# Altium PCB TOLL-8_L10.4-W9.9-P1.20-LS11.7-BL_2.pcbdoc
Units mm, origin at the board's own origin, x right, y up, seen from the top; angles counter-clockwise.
Board outline 22.84 x 25.35 mm, 2 copper layers (Top Layer, Bottom Layer), stack 0.07 mm thick; 1 components, 0 nets, 3 pads, 0 vias.
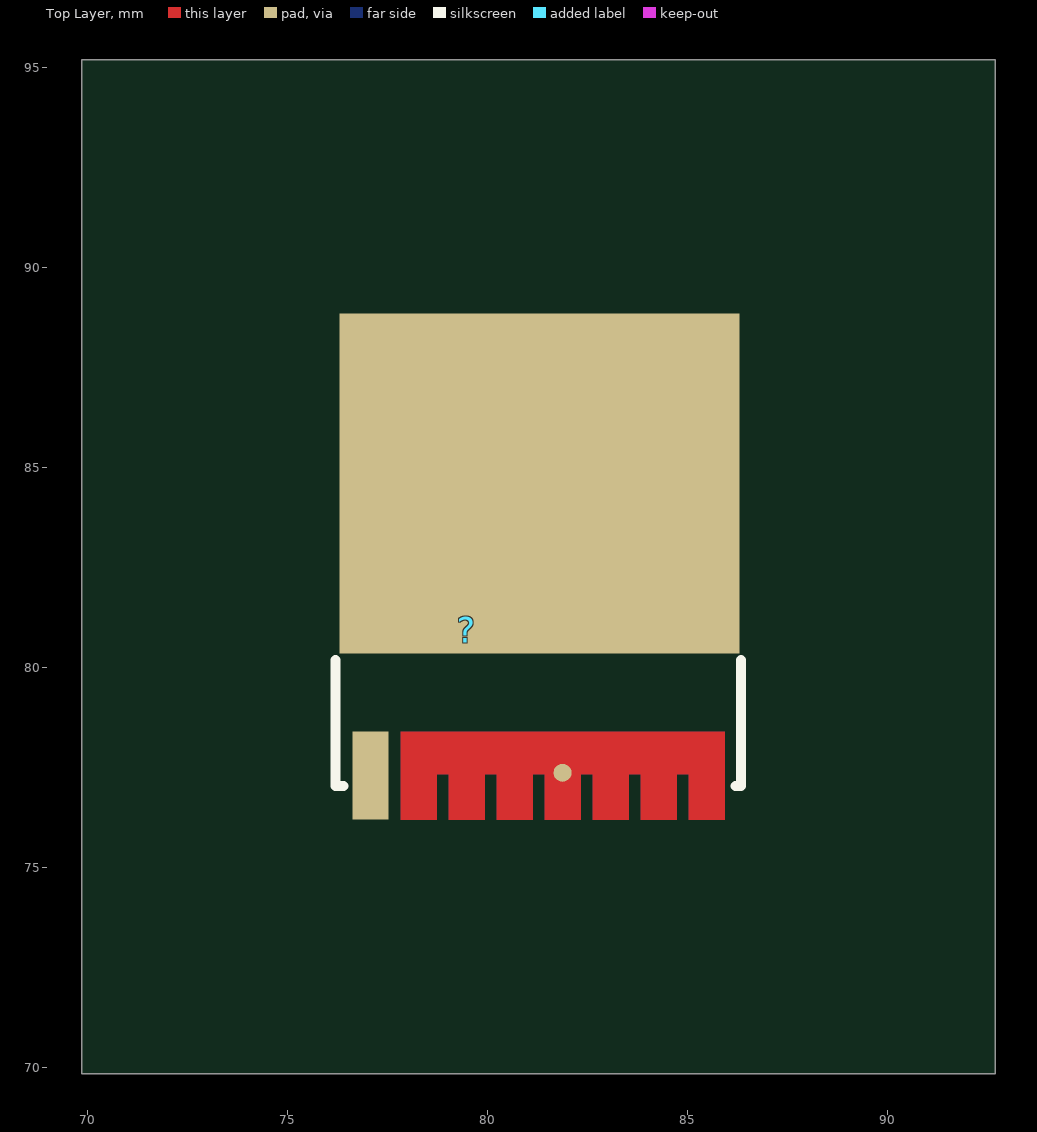
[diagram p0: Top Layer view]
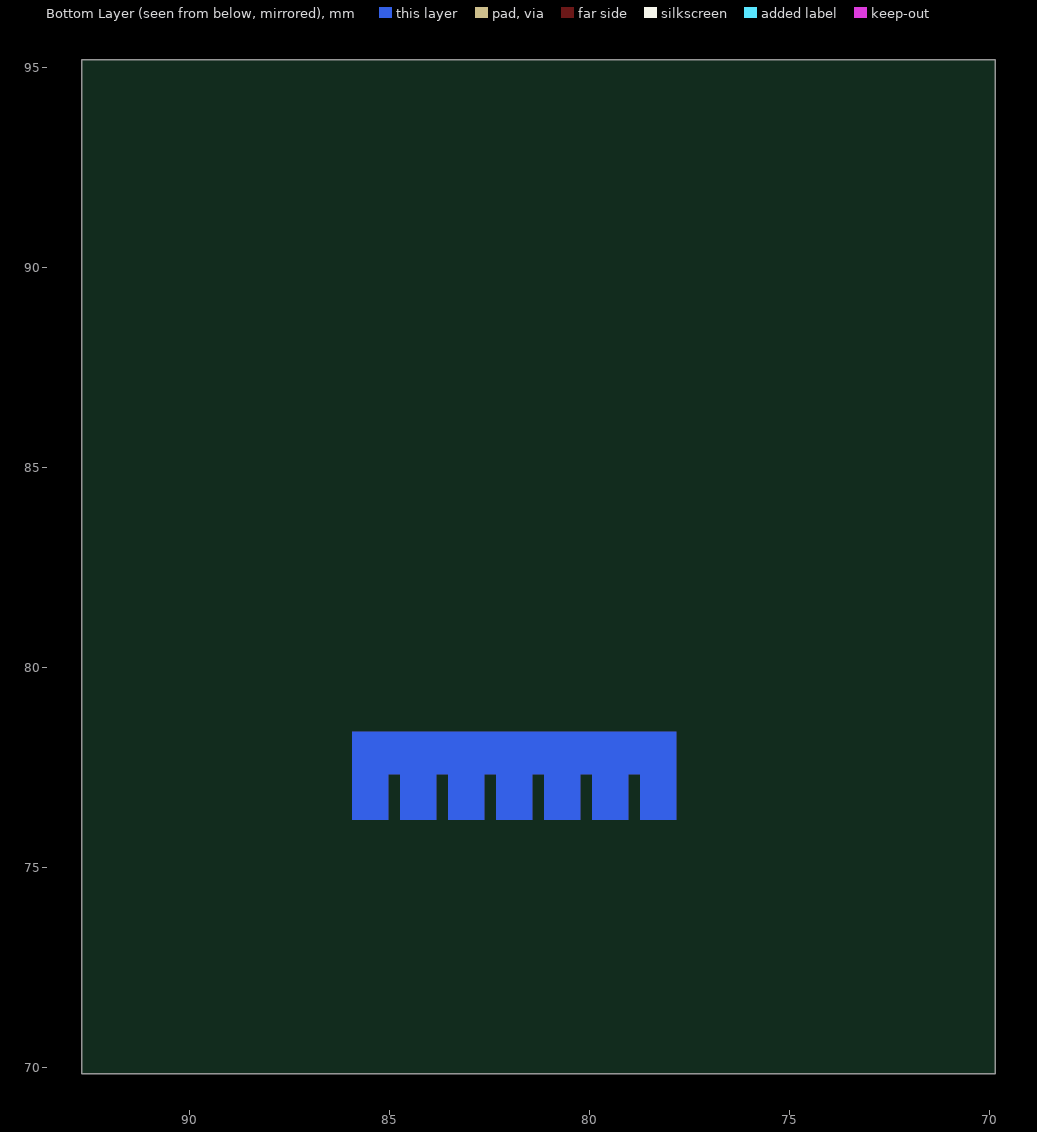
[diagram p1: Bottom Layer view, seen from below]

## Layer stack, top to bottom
Top Solder Mask Layer: solder mask 0.01, Dk 3.3
Top Layer: signal copper 0.035
Bottom Layer: signal copper 0.035
Bottom Solder Mask Layer: solder mask 0.01, Dk 3.3

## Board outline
92.69,69.85 69.85,69.85 69.85,95.2 92.69,95.2

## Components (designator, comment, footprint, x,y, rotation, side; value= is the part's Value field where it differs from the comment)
? "TOLL-8_L10.4-W9.9-P1.20-LS11.7-BL_2" TOLL-8_L10.4-W9.9-P1.20-LS11.7-BL_2 79.475,80.95 r0 top

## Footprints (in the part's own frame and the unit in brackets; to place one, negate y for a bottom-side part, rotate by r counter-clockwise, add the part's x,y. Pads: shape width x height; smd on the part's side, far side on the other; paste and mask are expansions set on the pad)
TOLL-8_L10.4-W9.9-P1.20-LS11.7-BL_2 [mm]
  rect 0.9x2.2 smd paste-100 mask+0.05: 1(-2.4,-3.65)
  round 0.451 smd: 2(2.4,-3.581)
  rect 10x8.5 smd paste-100 mask+0.05: 3(1.825,3.65)
  Top Layer region: -1.65,-2.55 -1.65,-4.75 -0.75,-4.75 -0.75,-3.615 -0.45,-3.615 -0.45,-4.75 0.45,-4.75 0.45,-3.615 0.75,-3.615 0.75,-4.75 1.65,-4.75 1.65,-3.615 1.95,-3.615 1.95,-4.75 2.85,-4.75 2.85,-3.615 3.15,-3.615 3.15,-4.75 4.05,-4.75 4.05,-3.615 4.35,-3.615 4.35,-4.75 5.25,-4.75 5.25,-3.615 5.55,-3.615 5.55,-4.75 6.45,-4.75 6.45,-3.615 6.45,-3.615 6.45,-2.551 6.45,-2.551 6.45,-2.55 5.55,-2.55 5.55,-2.551 5.25,-2.551 5.25,-2.55 4.35,-2.55 4.35,-2.551 4.05,-2.551 4.05,-2.55 3.15,-2.55 3.15,-2.551 2.85,-2.551 2.85,-2.55 1.95,-2.55 1.95,-2.551 1.65,-2.551 1.65,-2.55 0.75,-2.55 0.75,-2.551 0.45,-2.551 0.45,-2.55 -0.45,-2.55 -0.45,-2.551 -0.75,-2.551 -0.75,-2.55 -1.65,-2.55
  Bottom Layer region: -1.65,-2.55 -1.65,-4.75 -0.75,-4.75 -0.75,-3.615 -0.45,-3.615 -0.45,-4.75 0.45,-4.75 0.45,-3.615 0.75,-3.615 0.75,-4.75 1.65,-4.75 1.65,-3.615 1.95,-3.615 1.95,-4.75 2.85,-4.75 2.85,-3.615 3.15,-3.615 3.15,-4.75 4.05,-4.75 4.05,-3.615 4.35,-3.615 4.35,-4.75 5.25,-4.75 5.25,-3.615 5.55,-3.615 5.55,-4.75 6.45,-4.75 6.45,-3.615 6.45,-3.615 6.45,-2.551 6.45,-2.551 6.45,-2.55 5.55,-2.55 5.55,-2.551 5.25,-2.551 5.25,-2.55 4.35,-2.55 4.35,-2.551 4.05,-2.551 4.05,-2.55 3.15,-2.55 3.15,-2.551 2.85,-2.551 2.85,-2.55 1.95,-2.55 1.95,-2.551 1.65,-2.551 1.65,-2.55 0.75,-2.55 0.75,-2.551 0.45,-2.551 0.45,-2.55 -0.45,-2.55 -0.45,-2.551 -0.75,-2.551 -0.75,-2.55 -1.65,-2.55
  Multi-Layer region: -1.65,-2.55 -1.65,-4.75 -0.75,-4.75 -0.75,-3.615 -0.45,-3.615 -0.45,-4.75 0.45,-4.75 0.45,-3.615 0.75,-3.615 0.75,-4.75 1.65,-4.75 1.65,-3.615 1.95,-3.615 1.95,-4.75 2.85,-4.75 2.85,-3.615 3.15,-3.615 3.15,-4.75 4.05,-4.75 4.05,-3.615 4.35,-3.615 4.35,-4.75 5.25,-4.75 5.25,-3.615 5.55,-3.615 5.55,-4.75 6.45,-4.75 6.45,-3.615 6.45,-3.615 6.45,-2.551 6.45,-2.551 6.45,-2.55 5.55,-2.55 5.55,-2.551 5.25,-2.551 5.25,-2.55 4.35,-2.55 4.35,-2.551 4.05,-2.551 4.05,-2.55 3.15,-2.55 3.15,-2.551 2.85,-2.551 2.85,-2.55 1.95,-2.55 1.95,-2.551 1.65,-2.551 1.65,-2.55 0.75,-2.55 0.75,-2.551 0.45,-2.551 0.45,-2.55 -0.45,-2.55 -0.45,-2.551 -0.75,-2.551 -0.75,-2.55 -1.65,-2.55
  silkscreen extent -3.28,-3.91 6.86,-0.76

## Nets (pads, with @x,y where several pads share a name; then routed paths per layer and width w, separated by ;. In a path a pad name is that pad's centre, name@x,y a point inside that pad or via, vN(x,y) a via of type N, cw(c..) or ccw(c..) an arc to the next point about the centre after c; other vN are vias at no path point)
pads on no net: ?.1 ?.2 ?.3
